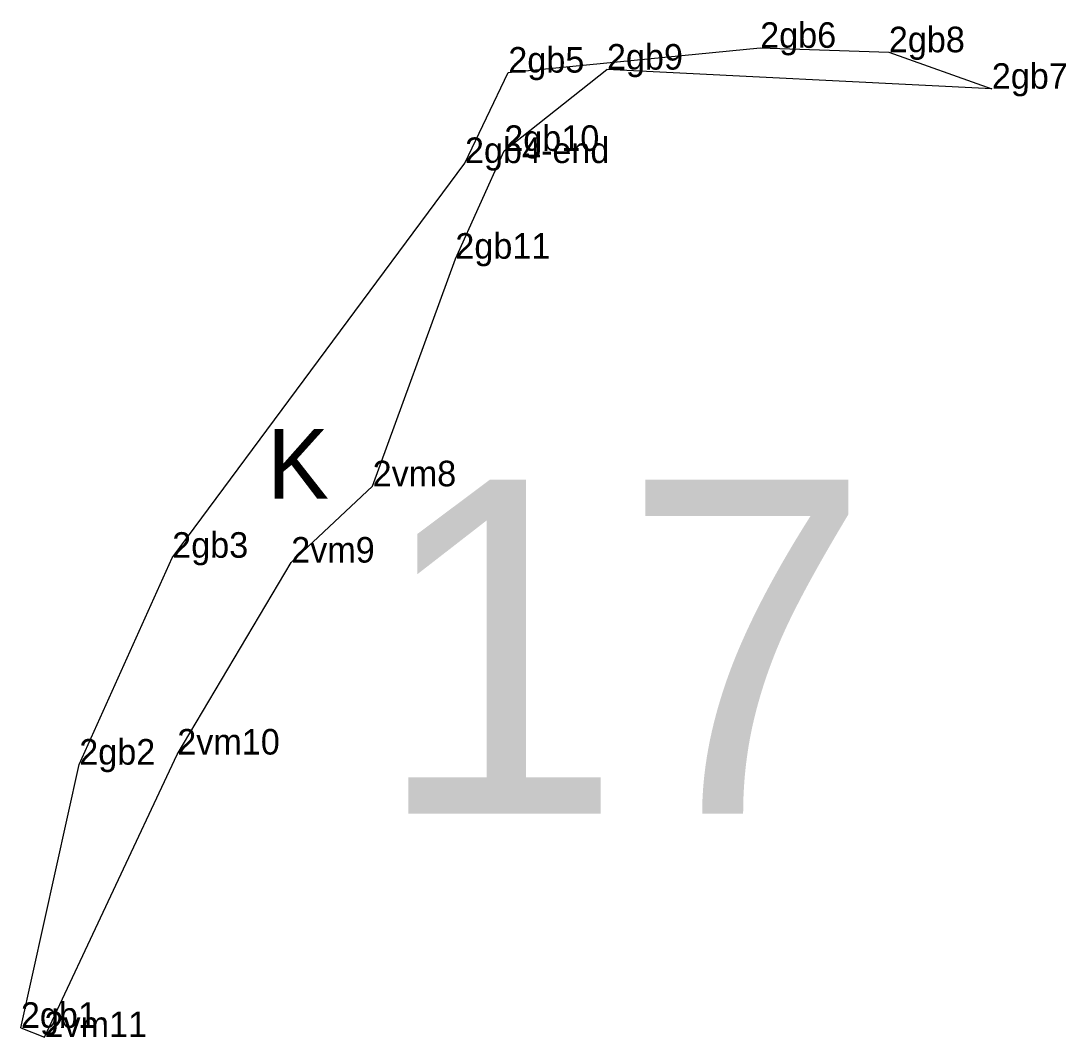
# Model space of a CAD drawing. Extents: x 2072529 to 2268796, y 436423 to 470397.
# Drawn here: x 2079464.5 to 2079669.1, y 465144.9 to 465343.7 of the extents above; entities that cross this region are included whole.
import ezdxf

# ---------------------------------------------------------------- set-up
doc = ezdxf.new("R2010")
doc.units = 0
for name, color, linetype in [('Default', 7, 'Continuous'), ('Exist Environmental Wetland Boundary', 7, 'Continuous'), ('Exist Environmental Wetland Boundary Cogo Comment', 7, 'Continuous'), ('Exist Environmental Wetland Boundary Cogo Point CELL', 7, 'Continuous'), ('Exist Hydro Swamp or Marsh', 7, 'Continuous')]:
    doc.layers.add(name, color=color, linetype=linetype)

msp = doc.modelspace()

# ---------------------------------------------------------------- linework, layer by layer
at = {"layer": 'Exist Environmental Wetland Boundary'}
for points in [[(2079551.43, 465315.9), (2079559.91, 465333.59), (2079609.2, 465338.44), (2079634.38, 465337.57), (2079654.53, 465330.43), (2079579.21, 465334.18)], [(2079533.36, 465252.65), (2079549.54, 465297.18), (2079559.12, 465318.27), (2079579.21, 465334.18)], [(2079464.52, 465146.69), (2079475.94, 465198.19), (2079494.13, 465238.67), (2079551.43, 465315.9)], [(2079464.52, 465146.69), (2079469.14, 465144.88), (2079495.12, 465200.16), (2079517.42, 465237.72), (2079533.36, 465252.65)]]:
    msp.add_lwpolyline(points, dxfattribs=at)
at = {"layer": 'Exist Environmental Wetland Boundary Cogo Point CELL'}
for p, q in [((2079609.2, 465338.44), (2079609.2, 465338.44)), ((2079634.38, 465337.57), (2079634.38, 465337.57)), ((2079559.91, 465333.59), (2079559.91, 465333.59)), ((2079579.21, 465334.18), (2079579.21, 465334.18)), ((2079654.53, 465330.43), (2079654.53, 465330.43)), ((2079559.12, 465318.27), (2079559.12, 465318.27)), ((2079551.43, 465315.9), (2079551.43, 465315.9)), ((2079549.54, 465297.18), (2079549.54, 465297.18)), ((2079533.36, 465252.65), (2079533.36, 465252.65)), ((2079494.13, 465238.67), (2079494.13, 465238.67)), ((2079517.42, 465237.72), (2079517.42, 465237.72)), ((2079495.12, 465200.16), (2079495.12, 465200.16)), ((2079475.94, 465198.19), (2079475.94, 465198.19)), ((2079464.52, 465146.69), (2079464.52, 465146.69)), ((2079469.14, 465144.88), (2079469.14, 465144.88))]:
    msp.add_line(p, q, dxfattribs=at)

# ---------------------------------------------------------------- texts
at = {"layer": 'Default'}
msp.add_text('17', height=65.34, dxfattribs=at).set_placement((2079533.68, 465188.59))
at = {"layer": 'Exist Environmental Wetland Boundary Cogo Comment'}
for s, p in [('2gb6', (2079609.2, 465338.44)), ('2gb8', (2079634.38, 465337.57)), ('2gb5', (2079559.91, 465333.59)), ('2gb9', (2079579.21, 465334.18)), ('2gb7', (2079654.53, 465330.43)), ('2gb10', (2079559.12, 465318.27)), ('2gb4-end', (2079551.43, 465315.9)), ('2gb11', (2079549.54, 465297.18)), ('2vm8', (2079533.36, 465252.65)), ('2gb3', (2079494.13, 465238.67)), ('2vm9', (2079517.42, 465237.72)), ('2vm10', (2079495.12, 465200.16)), ('2gb2', (2079475.94, 465198.19)), ('2gb1', (2079464.52, 465146.69)), ('2vm11', (2079469.14, 465144.88))]:
    msp.add_text(s, height=5, dxfattribs=at).set_placement(p)
at = {"layer": 'Exist Hydro Swamp or Marsh'}
msp.add_text('K', height=13.6, dxfattribs=at).set_placement((2079512.66, 465250.26))

doc.saveas('drawing.dxf')
